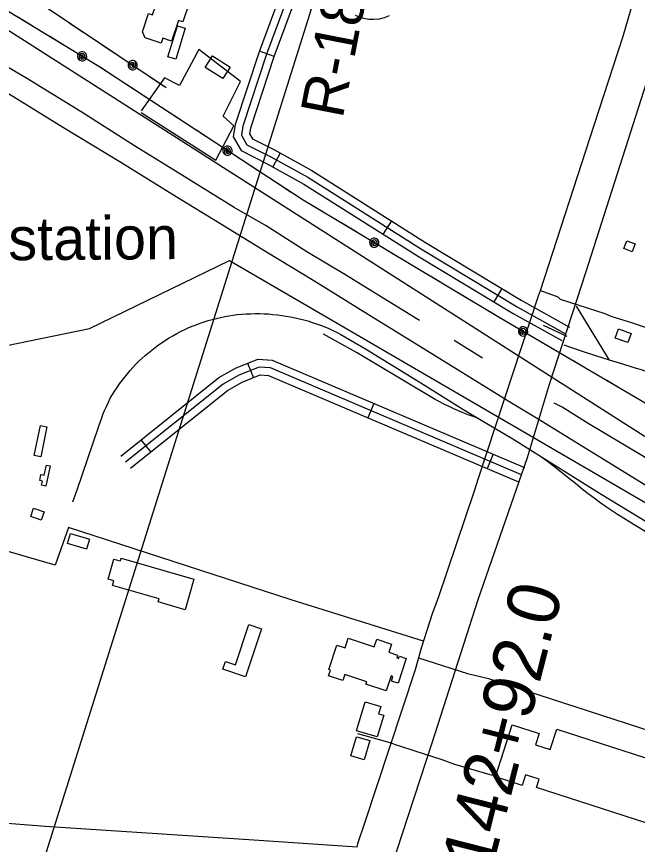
# Model space of a CAD drawing. Extents: x 3355677 to 3393573, y 612928 to 638357.
# Drawn here: x 3368073 to 3369270, y 625120 to 626715 of the extents above; entities that cross this region are included whole.
import ezdxf

# ---------------------------------------------------------------- set-up
doc = ezdxf.new("R2010")
doc.units = 0
for name, color, linetype in [('V-BLDG-OTLN', 7, 'Continuous'), ('V-DOMW-TANK', 7, 'Continuous'), ('V-RAIL-TRAK', 7, 'Continuous'), ('V-RIVR-RANG-IDEN', 7, 'Continuous'), ('V-ROAD-CNTR', 7, 'Continuous'), ('V-SITE-OTLN', 7, 'Continuous'), ('V-SITE-OTLN-IDEN', 7, 'Continuous'), ('V-SURV-IDEN', 7, 'Continuous'), ('V-TOPO-BNDY', 7, 'Continuous'), ('V-TOPO-SHOR', 7, 'Continuous'), ('V-UTIL-LINE', 7, 'Continuous')]:
    doc.layers.add(name, color=color, linetype=linetype)

msp = doc.modelspace()

# ---------------------------------------------------------------- linework, layer by layer
at = {"layer": 'V-BLDG-OTLN'}
for points in [[(3368361.7, 626800.6), (3368411.2, 626784.1), (3368398.5, 626746.2), (3368406.8, 626743.4), (3368394, 626704.9), (3368385.3, 626707.8), (3368372.1, 626668.2), (3368355.5, 626673.7), (3368352.2, 626663.8), (3368321.2, 626674.1), (3368315.9, 626686.1), (3368327.6, 626721.4), (3368335.7, 626718.7), (3368342.6, 626739.4), (3368333, 626742.7), (3368340.3, 626764.8), (3368348.9, 626761.9)], [(3368398.2, 626692.8), (3368380.1, 626633.2), (3368365.2, 626637.7), (3368383.4, 626697.4)], [(3368451.3, 626639.4), (3368485.1, 626618.1), (3368471, 626595.8), (3368437.2, 626617.1)], [(3369249.5, 626283.2), (3369265.4, 626277.4), (3369259.9, 626262.3), (3369244, 626268.1)], [(3369233.5, 626113.6), (3369258.2, 626104.9), (3369251.9, 626087), (3369227.2, 626095.7)], [(3368107.2, 625869.8), (3368119.3, 625927.1), (3368131.9, 625924.5), (3368119.9, 625867.1)], [(3368138, 625849.4), (3368129.8, 625810.7), (3368121.6, 625812.4), (3368123.2, 625820.3), (3368118, 625821.4), (3368120.4, 625832.7), (3368126.9, 625831.3), (3368131, 625850.9)], [(3368106.3, 625768.1), (3368126.3, 625761.1), (3368120.7, 625745.2), (3368100.7, 625752.1)], [(3368177.3, 625719.4), (3368213.9, 625708.2), (3368207.9, 625688.8), (3368171.3, 625700)], [(3368275.1, 625671.6), (3368415.3, 625631.2), (3368398.2, 625572.1), (3368346.1, 625587.2), (3368348, 625593.4), (3368258.3, 625619.3), (3368260.8, 625627.8), (3368249.7, 625631), (3368260.9, 625669.8), (3368273.6, 625666.2)], [(3368545.7, 625535.4), (3368514.9, 625443.2), (3368471, 625457.9), (3368475.8, 625472.5), (3368495.3, 625466), (3368521.2, 625543.6)], [(3368675.3, 625457), (3368690.7, 625504.2), (3368706.8, 625498.9), (3368712.8, 625517.2), (3368762.8, 625500.9), (3368767.5, 625515.4), (3368795.9, 625506.1), (3368790.8, 625490.4), (3368807.8, 625484.8), (3368806.1, 625479.6), (3368809.7, 625478.4), (3368811.2, 625482.8), (3368824.6, 625478.4), (3368809, 625430.7), (3368795.9, 625434.9), (3368798.9, 625443.9), (3368795.2, 625445.1), (3368785.7, 625415.9), (3368746.7, 625428.6), (3368748.3, 625433.5), (3368706, 625447.3), (3368702.3, 625436), (3368674.9, 625444.9), (3368678.5, 625456)], [(3368781, 625369), (3368768.7, 625327.3), (3368728.8, 625339), (3368745.2, 625394.7), (3368775.4, 625385.8), (3368771.3, 625371.8)], [(3368996.4, 625250.3), (3369028.7, 625350.4), (3369080.4, 625333.6), (3369073.4, 625312), (3369101.8, 625302.8), (3369114.5, 625342), (3369325.2, 625273.9), (3369320, 625257.8), (3369397.4, 625232.8), (3369377.8, 625172.1), (3369324.4, 625189.4), (3369318.8, 625171.8), (3369292.5, 625180.3), (3369286.5, 625161.7), (3369075.5, 625229.9), (3369080.6, 625245.5), (3369054.6, 625253.9), (3369048, 625233.6)], [(3368717.6, 625290.7), (3368728.5, 625327.6), (3368754.6, 625320), (3368743.7, 625283)]]:
    msp.add_lwpolyline(points, close=True, dxfattribs=at)
at = {"layer": 'V-DOMW-TANK'}
msp.add_lwpolyline([(3368791.5, 626716.9), (3368782, 626713.1), (3368772.1, 626710.6), (3368762.2, 626709.6), (3368752.4, 626709.9), (3368743, 626711.5), (3368734.4, 626714.1), (3368726.4, 626717.6)], dxfattribs=at)
at = {"layer": 'V-RAIL-TRAK'}
for points in [[(3368381.2, 626367.9), (3368274.4, 626434), (3368164.1, 626501.2), (3368066.5, 626561.2), (3367958.6, 626626.8), (3367897.4, 626665), (3367817, 626714), (3367729.9, 626768), (3367651.5, 626816.2), (3367560.7, 626872.3), (3367474.4, 626925.5), (3367384, 626980.8), (3367293.3, 627037.3), (3367208.9, 627088.6), (3367124.5, 627140.3), (3367039, 627192.8), (3366967.8, 627236.2), (3366858.7, 627303.8), (3366791.1, 627345.2), (3366693.5, 627405.2), (3366612, 627455.7), (3366499.2, 627524.5), (3366393.7, 627589)], [(3369351.5, 625771.5), (3369252.8, 625832.5), (3369156.1, 625891.9), (3369078.6, 625939.5), (3369027.6, 625970.6), (3368937.8, 626025.9), (3368848.7, 626080.8), (3368754.8, 626138.9), (3368646.4, 626206.1), (3368555.3, 626261.4), (3368465.4, 626316.3), (3368381.2, 626367.9)], [(3368411.7, 626118.5), (3368419.3, 626121.5), (3368427, 626124.4), (3368434.8, 626127), (3368442.6, 626129.5), (3368450.5, 626131.8), (3368458.5, 626133.8), (3368466.5, 626135.7), (3368474.6, 626137.3), (3368482.7, 626138.8), (3368490.8, 626140), (3368498.9, 626141), (3368507.5, 626141.8), (3368516.1, 626142.4), (3368524.7, 626142.8), (3368533.3, 626143), (3368541.9, 626142.9), (3368550.5, 626142.7), (3368559, 626142.2), (3368567.6, 626141.5), (3368576.2, 626140.7), (3368584.7, 626139.6), (3368593.2, 626138.3), (3368601.7, 626136.8), (3368610.1, 626135), (3368618.5, 626133.1), (3368626.8, 626131), (3368635.1, 626128.7), (3368643.3, 626126.1), (3368651.5, 626123.4), (3368659.5, 626120.5), (3368667.5, 626117.3), (3368675.5, 626114), (3368683.3, 626110.5), (3368691.1, 626106.8), (3368698.7, 626102.9)], [(3368182.1, 625780.3), (3368190.4, 625803.3), (3368231.4, 625923.8), (3368234, 625932), (3368236.9, 625940.2), (3368239.9, 625948.3), (3368243.2, 625956.3), (3368246.6, 625964.2), (3368250.3, 625972.1), (3368254.1, 625979.8), (3368258.3, 625986.9), (3368262.6, 625993.9), (3368267.2, 626000.7), (3368271.9, 626007.5), (3368276.7, 626014.1), (3368281.8, 626020.6), (3368287, 626027), (3368292.3, 626033.2), (3368297.8, 626039.3), (3368303.5, 626045.3), (3368309.3, 626051.1), (3368315.3, 626056.8), (3368321.4, 626062.3), (3368327.6, 626067.6), (3368334, 626072.8), (3368340.5, 626077.8), (3368347.1, 626082.7), (3368353.9, 626087.4), (3368360.7, 626091.9), (3368367.7, 626096.3), (3368374.8, 626100.4), (3368382, 626104.4), (3368389.3, 626108.2), (3368396.6, 626111.8), (3368404.1, 626115.3), (3368411.7, 626118.5)], [(3368962.7, 625941.6), (3368953.2, 625944.8), (3368943.8, 625948.1), (3368934.5, 625951.7), (3368925.2, 625955.5), (3368916, 625959.5), (3368907, 625963.7), (3368898, 625968.1), (3368889.1, 625972.7), (3368880.3, 625977.5), (3368814.9, 626016.8), (3368728.6, 626068), (3368664.8, 626103.3)], [(3368698.7, 626102.9), (3368746.1, 626075), (3368852.9, 626009.5), (3368933.5, 625959.1), (3368962.7, 625941.6), (3369029.8, 625901.3), (3369062.4, 625881.1), (3369085.2, 625866.9), (3369102.5, 625853.8), (3369119.7, 625840.5), (3369136.8, 625827), (3369153.7, 625813.4), (3369164.5, 625804.8), (3369175.3, 625796.3), (3369186.4, 625787.9), (3369197.5, 625779.8), (3369208.8, 625771.8), (3369220.2, 625764.1), (3369231.7, 625756.5), (3369243.4, 625749.1), (3369255.2, 625741.9), (3369358.7, 625678.4)], [(3369085.2, 625866.9), (3369200.4, 625795.3), (3369326.4, 625718.6), (3369456.4, 625637.6), (3369568, 625568.7), (3369690, 625494.2), (3369807.5, 625421.7), (3369904.3, 625362.7), (3370014.6, 625295.5), (3370106.5, 625238.2), (3370188.4, 625187.8), (3370285.5, 625129.6), (3370299.1, 625121.9), (3370312.8, 625114.4), (3370326.6, 625107), (3370340.5, 625099.8), (3370354.5, 625092.9), (3370368.5, 625086), (3370382.7, 625079.4), (3370396.9, 625073), (3370411.2, 625066.7), (3370476.9, 625033.1)]]:
    msp.add_lwpolyline(points, dxfattribs=at)
at = {"layer": 'V-ROAD-CNTR'}
for p, q in [((3368569.8, 626638.5), (3368541.7, 626648.9)), ((3368581.6, 626452), (3368567.1, 626425.8)), ((3368795.9, 626321.8), (3368779.9, 626296.4)), ((3369008.9, 626191.4), (3368993.4, 626165.8)), ((3369216, 626053.3), (3369152.7, 626157.2)), ((3369088.6, 626120.4), (3369134.3, 626099.3)), ((3368518.8, 626047.2), (3368530, 626019.3)), ((3368762.1, 625969.9), (3368750.4, 625942.3)), ((3368313.1, 625899.5), (3368331.9, 625876.1)), ((3368992.1, 625872), (3368980.4, 625844.4))]:
    msp.add_line(p, q, dxfattribs=at)
for points in [[(3371438.3, 633192.2), (3371329.9, 632861.6), (3371120.3, 632210.2), (3370873.5, 631453.5), (3370745.5, 631064.3), (3370611.1, 630643.9), (3370474.9, 630218.5), (3370241.9, 629509.3), (3370110.8, 629100.4), (3369991.2, 628758.8), (3369896.1, 628449.9), (3369849.7, 628302.3), (3369716.8, 627909.9), (3369502.8, 627231.5), (3369410.1, 626946.6), (3369287, 626587.1), (3369170, 626221.4), (3369099.9, 626006.1), (3369057.8, 625865), (3368962.5, 625591.4), (3368873.5, 625315.1), (3368759.9, 624967.5), (3368745.7, 624923.6)], [(3368794.2, 627407), (3368703, 627099.1), (3368620.9, 626819.8), (3368555.4, 626642.6), (3368509.5, 626503.9), (3368506.8, 626486.7), (3368517.3, 626468.5), (3368563.3, 626445), (3368634.9, 626405.6), (3368854, 626267.4), (3369038.4, 626156.1), (3369131.7, 626103.9)], [(3368804.2, 627388), (3368717.4, 627094.8), (3368635.1, 626815.1), (3368569.5, 626637.7), (3368524.2, 626500.4), (3368522.4, 626489.6), (3368528.1, 626479.8), (3368570.3, 626458.3), (3368642.5, 626418.5), (3368861.9, 626280.2), (3369045.9, 626169.1), (3369139.1, 626116.9)], [(3368752, 627317.4), (3368688.6, 627103.3), (3368606.6, 626824.5), (3368541.2, 626647.6), (3368494.9, 626507.5), (3368491.1, 626483.8), (3368506.5, 626457.1), (3368556.3, 626431.8), (3368627.3, 626392.7), (3368846.2, 626254.6), (3369030.8, 626143.2), (3369124.4, 626090.8)], [(3369314.3, 626020), (3369305.3, 626023.9), (3369296.2, 626027.6), (3369287.1, 626031.1), (3369277.8, 626034.3), (3369268.5, 626037.3), (3369242.2, 626045.2), (3369216, 626053.3), (3369189.9, 626061.6), (3369163.9, 626070.1), (3369128.6, 626082.2)], [(3368274.1, 625868.2), (3368463, 626019.6), (3368495.4, 626037.8), (3368538.2, 626055), (3368566.2, 626053.3), (3369052.4, 625846.3)], [(3369046.5, 625832.5), (3368562.7, 626038.5), (3368540.7, 626039.8), (3368501.9, 626024.2), (3368471.4, 626007.1), (3368283.5, 625856.5)], [(3368292.9, 625844.8), (3368479.8, 625994.7), (3368508.4, 626010.6), (3368543.1, 626024.7), (3368559.2, 626023.7), (3369040.6, 625818.7)]]:
    msp.add_lwpolyline(points, dxfattribs=at)
at = {"layer": 'V-SITE-OTLN'}
for points in [[(3370729.5, 626873.7), (3370829.3, 626518.1), (3370357, 626249.5), (3370645, 625589), (3370516.4, 625120.3), (3369107.7, 626018.5), (3367969.4, 626744.3)], [(3368313.6, 626530.4), (3368457.2, 626438.4), (3368492.4, 626504.8), (3368471.3, 626523.2), (3368505.1, 626590.4), (3368424.6, 626651.7), (3368387.3, 626582.3), (3368358.4, 626597.1), (3368313.4, 626533.9)]]:
    msp.add_lwpolyline(points, dxfattribs=at)
msp.add_lwpolyline([(3368804.9, 624989), (3368712, 624989.9), (3367780.4, 625064.2), (3367960.1, 626062.4), (3368213.9, 626114.2), (3368483.7, 626245.1), (3369427.8, 625696.1), (3370459.1, 625066.8), (3370383.7, 624758.4), (3369690.3, 624840.8), (3369383.4, 624901)], close=True, dxfattribs=at)
at = {"layer": 'V-TOPO-BNDY'}
msp.add_line((3370376.9, 632253.8), (3368006.8, 624710.9), dxfattribs=at)
at = {"layer": 'V-TOPO-SHOR'}
msp.add_line((3368971.5, 626057), (3368916.6, 626091.2), dxfattribs=at)
for points in [[(3368492.5, 626347.6), (3368396.4, 626407.4), (3368300.7, 626466.3), (3368197.6, 626532.1), (3368091.2, 626597), (3368003.7, 626647.8), (3367977.5, 626661.8), (3367972.3, 626667.4), (3367971, 626672.5), (3367963.7, 626681.9), (3367954.3, 626694.4), (3367949.3, 626700)], [(3368850.1, 626129.4), (3368779.7, 626172.7), (3368709.5, 626216.1), (3368632.8, 626262), (3368554.6, 626311.9), (3368492.5, 626347.6)], [(3370430.5, 625146.9), (3370337.5, 625209.3), (3370227.5, 625274.9), (3370157.3, 625314.7), (3370080.7, 625369.5), (3369985.6, 625429.2), (3369849.6, 625521.3), (3369783.8, 625559.4), (3369691.1, 625615.5), (3369553, 625699.5), (3369479.2, 625744.2), (3369405.3, 625788), (3369278.6, 625869.5), (3369175, 625931), (3369124.9, 625962.9), (3369109.9, 625970.2)]]:
    msp.add_lwpolyline(points, dxfattribs=at)
at = {"layer": 'V-UTIL-LINE'}
for points in [[(3370599.1, 625159.7), (3369954, 625561.1), (3369433, 625883.7), (3369003.6, 626135.6), (3368625.6, 626361.6), (3368231.9, 626619.3), (3367851.3, 626850.7), (3367382.4, 627145.7), (3366865, 627444.4), (3366480, 627712.3), (3366027.6, 627988.3), (3365574.4, 628269.8), (3365118.6, 628541.7), (3364545.7, 628879.7), (3364115.5, 629158.1), (3363633, 629456.1), (3363159.7, 629754.2), (3362684.9, 630044.1), (3362215.7, 630326.1), (3361710.6, 630626.7), (3361234.6, 630908.5), (3360733.5, 631217), (3359805.2, 631780.2)], [(3360754.9, 631203.8), (3361272.8, 630966.2), (3361739.5, 630687.3), (3362229.5, 630409.9), (3362725.1, 630088.2), (3363192.5, 629799.9), (3363660, 629518.9), (3364148.1, 629221.1), (3365159.2, 628623.7), (3365586.8, 628351.6), (3366029.2, 628054), (3366448.3, 627803.7), (3366902.5, 627514.5), (3367411.9, 627203.2), (3367902.7, 626885.8), (3368361.7, 626578.4)], [(3369083.2, 626187.2), (3369187, 626505.9), (3369242.3, 626677.9), (3369261.9, 626743.5), (3369350, 627005.6), (3369402.3, 627166), (3369421.5, 627226.5), (3369438.9, 627279.3), (3369492.5, 627442.3), (3369511.3, 627503.2), (3369524.9, 627541.3), (3369583.2, 627722.3), (3369665.3, 627972), (3369684, 628032), (3369703.6, 628092.5), (3369710.4, 628118.2), (3369762.3, 628276.5)], [(3368103.2, 626697.6), (3368074.2, 626715.2)], [(3368175, 626703.5), (3368203.2, 626684.5)], [(3368166.4, 626659.1), (3368137.4, 626676.8)], [(3368199.8, 626638.9), (3368199.9, 626636), (3368201.8, 626637.4), (3368201.5, 626640.2), (3368198.9, 626641.4), (3368197, 626638.6), (3368198, 626634), (3368202.2, 626633.5), (3368205.8, 626636.8), (3368204.9, 626641.3), (3368201.7, 626644.4), (3368196.9, 626643.7), (3368193.8, 626639.2), (3368195.1, 626631.2), (3368198.4, 626630), (3368201.9, 626630.1), (3368205.1, 626631.6), (3368207.5, 626634.2), (3368208.7, 626637.5), (3368208.5, 626641), (3368207, 626644.2), (3368204.4, 626646.5), (3368201.1, 626647.7), (3368197.6, 626647.6), (3368194.5, 626646.1), (3368192.1, 626643.5), (3368190.9, 626640.2), (3368191, 626636.7), (3368192.5, 626633.5), (3368195.1, 626631.2)], [(3368236.4, 626662.3), (3368264.7, 626643.3)], [(3368261.5, 626599.9), (3368233.1, 626618.6)], [(3368297.1, 626621.6), (3368297, 626624.5), (3368295.2, 626623.2), (3368295.3, 626620.4), (3368297.9, 626619.1), (3368299.9, 626621.8), (3368299.1, 626626.4), (3368294.9, 626627.1), (3368291.2, 626623.9), (3368291.9, 626619.4), (3368294.9, 626616.2), (3368299.7, 626616.6), (3368303.1, 626621), (3368302.1, 626629.1), (3368298.9, 626630.5), (3368295.3, 626630.5), (3368292.1, 626629.1), (3368289.6, 626626.6), (3368288.3, 626623.4), (3368288.3, 626619.9), (3368289.6, 626616.6), (3368292.1, 626614.2), (3368295.3, 626612.8), (3368298.8, 626612.8), (3368302.1, 626614.1), (3368304.6, 626616.6), (3368305.9, 626619.9), (3368305.9, 626623.4), (3368304.6, 626626.6), (3368302.1, 626629.1)], [(3368329.5, 626599.9), (3368357.7, 626581)], [(3368323.4, 626559.4), (3368295, 626578)], [(3368385.3, 626518.9), (3368356.9, 626537.5)], [(3368447.3, 626478.4), (3368418.8, 626497)], [(3368479.9, 626457), (3368480, 626454.1), (3368481.8, 626455.5), (3368481.7, 626458.2), (3368479.1, 626459.6), (3368477.1, 626456.8), (3368477.9, 626452.2), (3368482.2, 626451.6), (3368485.8, 626454.8), (3368485.1, 626459.3), (3368482, 626462.5), (3368477.2, 626462), (3368473.9, 626457.6), (3368475, 626449.5), (3368478.2, 626448.2), (3368481.7, 626448.2), (3368485, 626449.6), (3368487.4, 626452.1), (3368488.7, 626455.3), (3368488.7, 626458.8), (3368487.3, 626462.1), (3368484.8, 626464.5), (3368481.6, 626465.8), (3368478.1, 626465.8), (3368474.8, 626464.4), (3368472.4, 626461.9), (3368471.1, 626458.7), (3368471.1, 626455.2), (3368472.5, 626451.9), (3368475, 626449.5)], [(3368541, 626417), (3368512.5, 626435.6)], [(3368602.9, 626376.5), (3368574.4, 626395.1)], [(3368665.8, 626337.6), (3368636.6, 626355)], [(3368729.3, 626299.6), (3368700.1, 626317.1)], [(3368762.8, 626279.6), (3368763, 626276.7), (3368764.8, 626278.2), (3368764.6, 626280.9), (3368761.9, 626282.1), (3368760, 626279.3), (3368761, 626274.7), (3368765.3, 626274.3), (3368768.8, 626277.6), (3368767.9, 626282.1), (3368764.7, 626285.2), (3368759.9, 626284.5), (3368756.8, 626279.9), (3368758.2, 626271.9), (3368761.5, 626270.7), (3368765, 626270.9), (3368768.2, 626272.4), (3368770.5, 626275), (3368771.7, 626278.3), (3368771.5, 626281.8), (3368770, 626285), (3368767.4, 626287.3), (3368764.1, 626288.5), (3368760.6, 626288.3), (3368757.4, 626286.8), (3368755.1, 626284.2), (3368753.9, 626280.9), (3368754.1, 626277.4), (3368755.6, 626274.2), (3368758.2, 626271.9)], [(3368825.5, 626242.1), (3368796.3, 626259.6)], [(3368889, 626204.2), (3368859.8, 626221.6)], [(3368730, 625114.9), (3368731.8, 625123.7), (3368744, 625159.9), (3368792.6, 625307.2), (3368842.1, 625457.1), (3368854.3, 625500.9), (3368875.2, 625564.9), (3368887.3, 625597.7), (3368955.9, 625801.4), (3368963.7, 625825.8), (3369079.6, 626177.2), (3369083.2, 626187.2)], [(3369083.2, 626187.2), (3369116.4, 626175.2), (3369120.9, 626170.6), (3369207.4, 626142.9), (3369218.7, 626137.9), (3369260.3, 626125), (3369269.7, 626121.9), (3369421.9, 626071.3), (3369455.6, 626061.5), (3369460.5, 626063.3), (3369555.6, 626103), (3369622.1, 626126.6), (3369632.5, 626105)], [(3368952.5, 626166.2), (3368923.3, 626183.6)], [(3369016.1, 626128.3), (3369003.6, 626135.6), (3368986.8, 626145.7)], [(3369049.7, 626108.6), (3369049.9, 626105.7), (3369051.7, 626107.2), (3369051.4, 626109.9), (3369048.8, 626111.1), (3369046.9, 626108.3), (3369048, 626103.7), (3369052.2, 626103.3), (3369055.7, 626106.7), (3369054.8, 626111.1), (3369051.5, 626114.2), (3369046.7, 626113.4), (3369043.7, 626108.8), (3369045.1, 626100.8), (3369048.5, 626099.7), (3369052, 626099.9), (3369055.1, 626101.4), (3369057.5, 626104), (3369058.6, 626107.3), (3369058.4, 626110.8), (3369056.9, 626114), (3369054.3, 626116.3), (3369050.9, 626117.5), (3369047.4, 626117.3), (3369044.3, 626115.8), (3369041.9, 626113.1), (3369040.8, 626109.8), (3369041, 626106.3), (3369042.5, 626103.2), (3369045.1, 626100.8)], [(3369112.7, 626071.6), (3369083.3, 626088.8)], [(3369176.5, 626034.2), (3369147.2, 626051.4)], [(3369240.3, 625996.7), (3369211, 626014)], [(3368857.8, 625511.5), (3368602.6, 625591.5), (3368173.2, 625730.6), (3368148.1, 625658.2), (3368057.1, 625684.3), (3368035.3, 625606)], [(3368848.4, 625479.7), (3368942.7, 625449.3), (3368983.2, 625439.6), (3369298.1, 625337.9), (3369341, 625324), (3369352.3, 625356.9), (3369781.7, 625218.7)], [(3368730.5, 625333.5), (3368795.4, 625315.7), (3368801.1, 625313.4), (3368833.2, 625302.9), (3368841.1, 625300.2), (3368893.2, 625283.4), (3368917.4, 625274.5), (3368990, 625253.4)], [(3368730, 625114.7), (3368530.8, 625128.3), (3368128.3, 625154.8), (3367869.2, 625174.9)]]:
    msp.add_lwpolyline(points, dxfattribs=at)

# ---------------------------------------------------------------- texts
at = {"layer": 'V-RIVR-RANG-IDEN'}
msp.add_text('R-187.0', height=83, rotation=79.0102, dxfattribs=at).set_placement((3368701.6, 626516.8))
at = {"layer": 'V-SITE-OTLN-IDEN'}
msp.add_text('Substation', height=83, rotation=0.3981, dxfattribs=at).set_placement((3367860.3, 626244.3))
at = {"layer": 'V-SURV-IDEN'}
msp.add_text('2142+92.0', height=100, rotation=75.7263, dxfattribs=at).set_placement((3368970.3, 624992.3))

doc.saveas('drawing.dxf')
